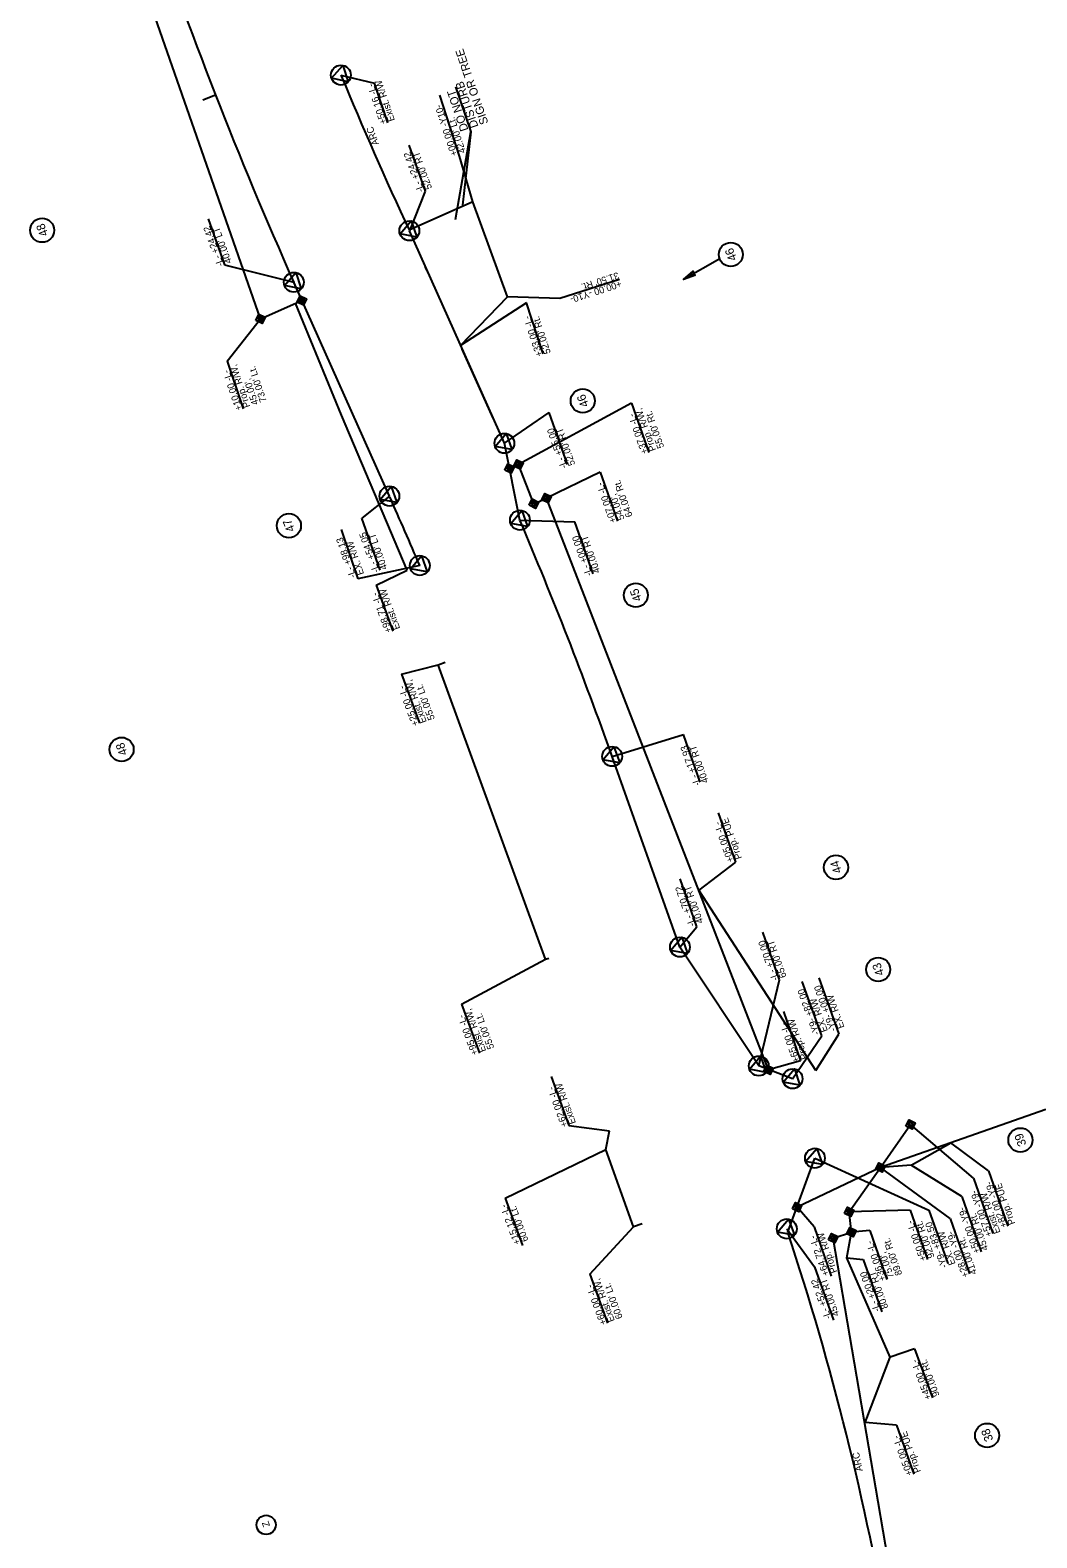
# Model space of a CAD drawing. Extents: x 1610947 to 1617684, y 899814 to 904658.
# Drawn here: x 1616090 to 1616822, y 902704 to 903801 of the extents above; entities that cross this region are included whole.
import ezdxf

# ---------------------------------------------------------------- set-up
doc = ezdxf.new("R2010")
doc.units = 0
for name, color, linetype in [('Default', 7, 'Continuous'), ('Prop Conc 1ft 6in Curb and Gutter', 7, 'Continuous'), ('Prop Dimension', 7, 'Continuous'), ('Prop EOT Dash', 7, 'Continuous'), ('Prop Hatching', 7, 'Continuous'), ('Prop Horizontal Alignment Curve and Spiral Data', 7, 'Continuous'), ('Prop Horizontal Alignment Direction Label', 7, 'Continuous'), ('Prop Horizontal Alignment Tick Label', 7, 'Continuous'), ('Prop Horizontal Alignment Tick Large', 7, 'Continuous'), ('Prop ROW Marker CELL', 7, 'Continuous'), ('Prop ROW RW Lines', 7, 'Continuous'), ('Prop ROW Station Offsets', 7, 'Continuous'), ('Prop Terminator CELL', 7, 'Continuous'), ('Scratch_Level_3', 7, 'Continuous'), ('Typical Terminator CELL', 7, 'Continuous')]:
    doc.layers.add(name, color=color, linetype=linetype)

msp = doc.modelspace()

# ---------------------------------------------------------------- linework, layer by layer
at = {"layer": 'Default'}
msp.add_circle((1616261.7, 902713.8), 7, dxfattribs=at)
at = {"layer": 'Prop Conc 1ft 6in Curb and Gutter'}
for p, q in [((1616402.3, 903709.6), (1616388, 903753.9)), ((1616412.1, 903676.4), (1616402.3, 903709.6)), ((1616518.8, 903620), (1616475.4, 903606)), ((1616475.4, 903606), (1616437.2, 903607.3)), ((1616451.2, 903602.9), (1616403.2, 903571.9)), ((1616463.2, 903565.7), (1616451.2, 903602.9)), ((1616341.8, 903397.5), (1616353.9, 903364.1)), ((1616360.3, 903332.8), (1616386.9, 903339.5)), ((1616360.3, 903332.8), (1616373.3, 903297.1)), ((1616590.5, 903231.8), (1616603, 903196)), ((1616603, 903196), (1616576.5, 903175.5)), ((1616403.9, 903092.6), (1616465, 903125.3)), ((1616663.7, 903111.7), (1616678.2, 903070.9)), ((1616403.9, 903092.6), (1616416.9, 903056.9)), ((1616661.6, 903044.5), (1616678.2, 903070.9)), ((1616469.1, 903040.1), (1616481.8, 903004.4)), ((1616787.2, 902971.5), (1616759.8, 902991.8)), ((1616435.7, 902951.6), (1616508.9, 902987)), ((1616767.7, 902952.8), (1616730.9, 902975.4)), ((1616787.2, 902971.5), (1616801.3, 902931.2)), ((1616435.7, 902951.6), (1616448.3, 902917.1)), ((1616767.7, 902952.8), (1616781.8, 902912.5)), ((1616497.1, 902896.1), (1616529, 902930.6)), ((1616684, 902908.1), (1616696, 902906.8)), ((1616696, 902906.8), (1616709.5, 902868.9)), ((1616497.1, 902896.1), (1616510.1, 902860.5)), ((1616733.3, 902841.8), (1616746.3, 902806.2)), ((1616720.1, 902786.4), (1616732.7, 902750.7))]:
    msp.add_line(p, q, dxfattribs=at)
for points in [[(1616341.8, 903397.5), (1616364.4, 903408.5)], [(1616481.8, 903004.4), (1616511.4, 903000.6)], [(1616733.3, 902841.8), (1616715.6, 902835.9)], [(1616720.1, 902786.4), (1616697.4, 902788.2)]]:
    msp.add_lwpolyline(points, dxfattribs=at)
at = {"layer": 'Prop Dimension'}
for p, q in [((1616399.4, 903760), (1616410.5, 903727.3)), ((1616399.4, 903663.6), (1616410.5, 903727.3)), ((1616410.5, 903727.3), (1616404.5, 903674))]:
    msp.add_line(p, q, dxfattribs=at)
at = {"layer": 'Prop EOT Dash'}
for points in [[(1616284.4, 903603.5), (1616286.5, 903608.1), (1616291.2, 903605.9), (1616289, 903601.3)], [(1616286.1, 903604.1), (1616287.2, 903606.4), (1616289.5, 903605.3), (1616288.4, 903603)], [(1616254.3, 903590), (1616256.4, 903594.6), (1616261, 903592.5), (1616258.9, 903587.9)], [(1616256, 903590.6), (1616257, 903592.9), (1616259.3, 903591.9), (1616258.3, 903589.6)], [(1616435.3, 903481.2), (1616437.5, 903485.8), (1616442.1, 903483.6), (1616439.9, 903479)], [(1616437, 903481.8), (1616438.1, 903484.1), (1616440.4, 903483), (1616439.3, 903480.7)], [(1616441.8, 903484), (1616444, 903488.6), (1616448.6, 903486.4), (1616446.4, 903481.8)], [(1616443.5, 903484.6), (1616444.6, 903486.9), (1616446.9, 903485.8), (1616445.8, 903483.5)], [(1616462.2, 903459.5), (1616464.4, 903464.1), (1616469, 903461.9), (1616466.8, 903457.3)], [(1616463.9, 903460.1), (1616465, 903462.4), (1616467.3, 903461.3), (1616466.2, 903459)], [(1616453, 903455.6), (1616455.2, 903460.2), (1616459.8, 903458), (1616457.6, 903453.4)], [(1616454.7, 903456.2), (1616455.8, 903458.5), (1616458.1, 903457.4), (1616457, 903455.1)], [(1616623.8, 903043.7), (1616626, 903048.3), (1616630.6, 903046.2), (1616628.4, 903041.6)], [(1616625.5, 903044.3), (1616626.6, 903046.6), (1616628.9, 903045.6), (1616627.8, 903043.3)], [(1616727.1, 903004), (1616729.3, 903008.6), (1616733.9, 903006.4), (1616731.7, 903001.8)], [(1616728.8, 903004.6), (1616729.9, 903006.9), (1616732.2, 903005.8), (1616731.1, 903003.5)], [(1616705.2, 902972.6), (1616707.4, 902977.2), (1616712, 902975), (1616709.8, 902970.4)], [(1616706.9, 902973.2), (1616708, 902975.5), (1616710.3, 902974.4), (1616709.2, 902972.1)], [(1616644.5, 902943.8), (1616646.7, 902948.4), (1616651.2, 902946.2), (1616649.1, 902941.6)], [(1616646.2, 902944.4), (1616647.3, 902946.7), (1616649.6, 902945.6), (1616648.5, 902943.3)], [(1616682.4, 902940.4), (1616684.6, 902945), (1616689.2, 902942.8), (1616687, 902938.2)], [(1616684.1, 902941), (1616685.2, 902943.3), (1616687.5, 902942.2), (1616686.4, 902939.9)], [(1616670.8, 902921.2), (1616673, 902925.8), (1616677.6, 902923.6), (1616675.4, 902919)], [(1616672.5, 902921.8), (1616673.6, 902924.1), (1616675.9, 902923), (1616674.8, 902920.7)], [(1616684.1, 902925.5), (1616686.3, 902930.1), (1616690.9, 902927.9), (1616688.7, 902923.3)], [(1616685.8, 902926.1), (1616686.9, 902928.4), (1616689.2, 902927.3), (1616688.1, 902925)]]:
    msp.add_lwpolyline(points, close=True, dxfattribs=at)
at = {"layer": 'Prop Hatching'}
msp.add_line((1616591.6, 903634.9), (1616565.3, 903620), dxfattribs=at)
for centre in [(1616098.8, 903655.7), (1616599.7, 903638.1), (1616492, 903531.6), (1616278.3, 903440.8), (1616530.6, 903390.2), (1616156.6, 903278), (1616676.2, 903192.2), (1616706.9, 903117.9), (1616810.3, 902993.8), (1616786.1, 902778.9)]:
    msp.add_circle(centre, 8.75, dxfattribs=at)
at = {"layer": 'Prop Horizontal Alignment Curve and Spiral Data'}
for p, q in [((1616776.2, 902966), (1616730.5, 903005.2)), ((1616776.2, 902966), (1616790.3, 902925.8)), ((1616660.3, 902930.6), (1616647.9, 902945)), ((1616660.3, 902930.6), (1616672.8, 902894.8))]:
    msp.add_line(p, q, dxfattribs=at)
at = {"layer": 'Prop Horizontal Alignment Direction Label'}
for p, q in [((1616257.7, 903591.2), (1616125.4, 903970.5)), ((1616257.7, 903591.2), (1616287.8, 903604.7)), ((1616438.7, 903482.4), (1616445.2, 903485.2)), ((1616456.4, 903456.8), (1616445.2, 903485.2)), ((1616456.4, 903456.8), (1616465.6, 903460.7)), ((1616627.2, 903045), (1616465.6, 903460.7)), ((1616685.8, 902941.6), (1616708.6, 902973.8)), ((1616687.5, 902926.7), (1616685.8, 902941.6)), ((1616674.2, 902922.4), (1616687.5, 902926.7)), ((1616749.1, 902482.9), (1616674.2, 902922.4))]:
    msp.add_line(p, q, dxfattribs=at)
at = {"layer": 'Prop Horizontal Alignment Tick Label'}
for p, q in [((1616233.3, 903560.5), (1616245, 903525.7)), ((1616527.5, 903529.9), (1616540, 903494.1)), ((1616504.7, 903479.8), (1616517.2, 903444)), ((1616638, 903087.3), (1616650.5, 903051.5)), ((1616759.3, 902936.8), (1616708.6, 902973.8)), ((1616730.1, 902942.8), (1616742.7, 902907)), ((1616759.3, 902936.8), (1616773.4, 902896.5)), ((1616700.7, 902928.1), (1616713.2, 902892.3))]:
    msp.add_line(p, q, dxfattribs=at)
for points in [[(1616233.3, 903560.5), (1616257.7, 903591.2)], [(1616527.5, 903529.9), (1616445.2, 903485.2)], [(1616504.7, 903479.8), (1616465.6, 903460.7)], [(1616650.5, 903051.5), (1616627.2, 903045)], [(1616730.1, 902942.8), (1616685.8, 902941.6)], [(1616700.7, 902928.1), (1616687.5, 902926.7)]]:
    msp.add_lwpolyline(points, dxfattribs=at)
at = {"layer": 'Prop Horizontal Alignment Tick Large'}
for q in [(1616730.5, 903005.2), (1616647.9, 902945)]:
    msp.add_line((1616708.6, 902973.8), q, dxfattribs=at)
at = {"layer": 'Prop ROW Marker CELL'}
for p, q in [((1616316.1, 903768.6), (1616316.1, 903768.6)), ((1616365.9, 903655.4), (1616365.9, 903655.4)), ((1616281.9, 903617.9), (1616281.9, 903617.9)), ((1616287.8, 903604.7), (1616287.8, 903604.7)), ((1616257.7, 903591.2), (1616257.7, 903591.2)), ((1616435, 903500.7), (1616435, 903500.7)), ((1616445.2, 903485.2), (1616445.2, 903485.2)), ((1616438.7, 903482.4), (1616438.7, 903482.4)), ((1616351.4, 903462.3), (1616351.4, 903462.3)), ((1616456.4, 903456.8), (1616456.4, 903456.8)), ((1616465.6, 903460.7), (1616465.6, 903460.7)), ((1616446.3, 903444.8), (1616446.3, 903444.8)), ((1616373.5, 903411.8), (1616373.5, 903411.8)), ((1616513.4, 903272.9), (1616513.4, 903272.9)), ((1616562.7, 903134.2), (1616562.7, 903134.2)), ((1616620, 903047.7), (1616620, 903047.7)), ((1616627.2, 903045), (1616627.2, 903045)), ((1616644.6, 903038.4), (1616644.6, 903038.4)), ((1616730.5, 903005.2), (1616730.5, 903005.2)), ((1616660.9, 902980.6), (1616660.9, 902980.6)), ((1616708.6, 902973.8), (1616708.6, 902973.8)), ((1616647.9, 902945), (1616647.9, 902945)), ((1616685.8, 902941.6), (1616685.8, 902941.6)), ((1616640.4, 902929.2), (1616640.4, 902929.2)), ((1616687.5, 902926.7), (1616687.5, 902926.7)), ((1616674.2, 902922.4), (1616674.2, 902922.4))]:
    msp.add_line(p, q, dxfattribs=at)
for points in [[(1616321.5, 903763.8), (1616309.3, 903766.3), (1616317.6, 903775.6)], [(1616371.3, 903650.6), (1616359.1, 903653.1), (1616367.3, 903662.5)], [(1616287.3, 903613.1), (1616275.1, 903615.6), (1616283.3, 903624.9)], [(1616440.5, 903496.1), (1616428.2, 903498.3), (1616436.3, 903507.8)], [(1616356.9, 903457.6), (1616344.6, 903459.9), (1616352.7, 903469.4)], [(1616451.8, 903440.1), (1616439.6, 903442.4), (1616447.6, 903451.9)], [(1616378.9, 903407.1), (1616366.7, 903409.3), (1616374.8, 903418.8)], [(1616518.9, 903268.2), (1616506.6, 903270.5), (1616514.7, 903280)], [(1616568.2, 903129.5), (1616555.9, 903131.8), (1616564, 903141.3)], [(1616625.5, 903043), (1616613.2, 903045.3), (1616621.3, 903054.8)], [(1616650, 903033.8), (1616637.8, 903036), (1616645.9, 903045.5)], [(1616666.4, 902975.9), (1616654.1, 902978.2), (1616662.2, 902987.7)], [(1616645.9, 902924.5), (1616633.6, 902926.7), (1616641.7, 902936.2)]]:
    msp.add_lwpolyline(points, close=True, dxfattribs=at)
for centre in [(1616316.1, 903768.6), (1616365.9, 903655.4), (1616281.9, 903617.9), (1616435, 903500.7), (1616351.4, 903462.3), (1616446.3, 903444.8), (1616373.5, 903411.8), (1616513.4, 903272.9), (1616562.7, 903134.2), (1616620, 903047.7), (1616644.6, 903038.4), (1616660.9, 902980.6), (1616640.4, 902929.2)]:
    msp.add_circle(centre, 7.2, dxfattribs=at)
at = {"layer": 'Prop ROW RW Lines'}
for p, q in [((1616435, 903500.7), (1616365.9, 903655.4)), ((1616378.9, 903626.3), (1616377.7, 903628.9)), ((1616351.4, 903462.3), (1616281.9, 903617.9)), ((1616426.9, 903519), (1616404.4, 903569.2)), ((1616446.3, 903444.8), (1616435, 903500.7)), ((1616562.7, 903134.2), (1616513.4, 903272.9)), ((1616620, 903047.7), (1616562.7, 903134.2)), ((1616644.6, 903038.4), (1616620, 903047.7)), ((1616641.2, 902926.8), (1616660.9, 902980.6))]:
    msp.add_line(p, q, dxfattribs=at)
for centre, radius, start, end in [((1619057.3, 904858.2), 3040, 198.4827, 204.0803), ((1619039, 904898.5), 2948, 202.5367, 204.9392), ((1613649, 902254.6), 2960, 23.0123, 24.0665), ((1613649, 902254.6), 3040, 19.5707, 23.048), ((1614715.5, 902288.7), 2028.6, 9.6706, 18.3345)]:
    msp.add_arc(centre, radius, start, end, dxfattribs=at)
at = {"layer": 'Prop ROW Station Offsets'}
for p, q in [((1616316.1, 903768.6), (1616340.5, 903762.7)), ((1616350.2, 903733.8), (1616340.5, 903762.7)), ((1616365.4, 903717.6), (1616377.4, 903684.1)), ((1616377.4, 903684.1), (1616365.9, 903655.4)), ((1616219.5, 903664.1), (1616231.5, 903630.6)), ((1616435, 903500.7), (1616467.7, 903523.2)), ((1616481, 903485.3), (1616467.7, 903523.2)), ((1616351.4, 903462.3), (1616331.4, 903446.2)), ((1616344.6, 903408.3), (1616331.4, 903446.2)), ((1616446.3, 903444.8), (1616486.3, 903443.6)), ((1616499.6, 903405.7), (1616486.3, 903443.6)), ((1616316.3, 903437.9), (1616328.5, 903402.1)), ((1616373.5, 903411.8), (1616328.5, 903402.1)), ((1616513.4, 903272.9), (1616565.3, 903288.9)), ((1616577.5, 903254.1), (1616565.3, 903288.9)), ((1616575.1, 903148.9), (1616562.8, 903183.9)), ((1616562.7, 903134.2), (1616575.1, 903148.9)), ((1616635.2, 903110.4), (1616622.9, 903145)), ((1616620, 903047.7), (1616635.2, 903110.4)), ((1616665.8, 903069.5), (1616651.6, 903109.2)), ((1616644.6, 903038.4), (1616665.8, 903069.5)), ((1616660.9, 902980.6), (1616743.7, 902942.7)), ((1616743.7, 902942.7), (1616757.5, 902903.9)), ((1616640.4, 902929.2), (1616660.5, 902901.5)), ((1616660.5, 902901.5), (1616674.3, 902862.7))]:
    msp.add_line(p, q, dxfattribs=at)
msp.add_lwpolyline([(1616231.5, 903630.6), (1616281.9, 903617.9)], dxfattribs=at)
at = {"layer": 'Prop Terminator CELL'}
msp.add_lwpolyline([(1616573.9, 903623.1), (1616565.3, 903620), (1616572.4, 903625.9), (1616572.2, 903623.9)], close=True, dxfattribs=at)
msp.add_lwpolyline([(1616573.9, 903623.1), (1616565.3, 903620), (1616572.4, 903625.9), (1616572.2, 903623.9)], close=True, dxfattribs=at)
at = {"layer": 'Scratch_Level_3'}
for p, q in [((1616225, 903754), (1616215.7, 903750.3)), ((1616412.1, 903676.4), (1616365.7, 903655.9)), ((1616437.2, 903607.3), (1616412.1, 903676.4)), ((1616403.2, 903571.9), (1616437.2, 903607.3)), ((1616316.5, 903521.2), (1616283.2, 903602.7)), ((1616364.4, 903408.5), (1616316.5, 903521.2)), ((1616386.9, 903339.5), (1616391.9, 903341.4)), ((1616465, 903125.3), (1616386.9, 903339.5)), ((1616661.6, 903044.5), (1616576.5, 903175.5)), ((1616465, 903125.3), (1616467.4, 903126.1)), ((1616508.9, 902987), (1616511.4, 903000.6)), ((1616730.9, 902975.4), (1616759.8, 902991.8)), ((1616529, 902930.6), (1616508.9, 902987)), ((1616730.9, 902975.4), (1616708.6, 902973.8)), ((1616535.2, 902932.8), (1616529, 902930.6)), ((1616684, 902908.1), (1616687.5, 902926.7)), ((1616715.6, 902835.9), (1616684, 902908.1)), ((1616697.4, 902788.2), (1616715.6, 902835.9))]:
    msp.add_line(p, q, dxfattribs=at)
at = {"layer": 'Typical Terminator CELL'}
msp.add_line((1616828.9, 903016), (1616708.6, 902973.8), dxfattribs=at)

# ---------------------------------------------------------------- texts
at = {"layer": 'Default'}
msp.add_text('Z', height=5, rotation=109.5707, dxfattribs=at).set_placement((1616264.6, 902713.2))
at = {"layer": 'Prop Conc 1ft 6in Curb and Gutter'}
for s, rotation, p in [('+00.00 -Y10-', 107.893, (1616401, 903710.6)), ("42.00' Lt.", 107.893, (1616407, 903712.6)), ('+00.00 -Y10-', 197.893, (1616519.3, 903619.3)), ("31.50' Rt.", 197.893, (1616517.4, 903625.3)), ('+33.00 -L-', 107.893, (1616462.9, 903564.7)), ("52.00' Rt.", 107.893, (1616468.8, 903566.6)), ('+98.71 -L-', 110.0511, (1616353.2, 903363.9)), ('Exist. R/W', 110.0511, (1616359.3, 903366.1)), ('+25.00 -L-', 110.0511, (1616372.8, 903296)), ('Exist. R/W,', 110.0511, (1616378.6, 903298.1)), ("55.00' Lt.", 110.0511, (1616384.5, 903300.3)), ('+05.00 -L-', 109.3048, (1616602, 903196.9)), ('Prop. PUE', 109.3048, (1616607.9, 903199)), ('-Y9- +00.00', 109.5486, (1616676.5, 903073.8)), ('Exist. R/W,', 110.0511, (1616421.8, 903058.7)), ('EX. R/W', 109.5486, (1616682.4, 903075.9)), ('+95.00 -L-', 110.0511, (1616416, 903056.6)), ("55.00' Lt.", 110.0511, (1616427.7, 903060.9)), ('Exist. R/W', 109.5486, (1616487.1, 903006.3)), ('+62.00 -L-', 109.5486, (1616481.2, 903004.2)), ('+82.00 -Y9-', 109.3048, (1616800.8, 902931)), ('Prop. PUE', 109.3048, (1616806.7, 902933.1)), ('+15.12 -L-', 110.0511, (1616446.8, 902918.7)), ("60.00' Lt.", 110.0511, (1616452.6, 902920.8)), ('+50.00 -Y9-', 109.3048, (1616781.2, 902912.3)), ("45.00' Rt.", 109.3048, (1616787.1, 902914.3)), ('Exist. R/W,', 110.0511, (1616515.4, 902862.4)), ('-L- +20.00', 109.5486, (1616708.4, 902869.8)), ("80.00' RT", 109.5486, (1616714.3, 902871.9)), ('+60.00 -L-', 110.0511, (1616509.5, 902860.3)), ("60.00' Lt.", 110.0511, (1616521.2, 902864.6)), ('+45.00 -L-', 110.0511, (1616745.7, 902805.9)), ("90.00' Rt.", 110.0511, (1616751.6, 902808.1)), ('Prop. PUE', 109.4757, (1616738, 902752.6)), ('+05.00 -L-', 109.4757, (1616732.1, 902750.5))]:
    msp.add_text(s, height=5, rotation=rotation, dxfattribs=at).set_placement(p)
at = {"layer": 'Prop Dimension'}
for s, p in [('SIGN OR TREE', (1616423.4, 903733.8)), ('DISTURB', (1616416.2, 903731.3)), ('DO NOT ', (1616408.9, 903728.9))]:
    msp.add_text(s, height=6, rotation=108.7326, dxfattribs=at).set_placement(p)
at = {"layer": 'Prop Hatching'}
for s, rotation, p in [('48', 111.3527, (1616103.4, 903652.6)), ('46', 111.3527, (1616604.3, 903634.8)), ('46', 110.62, (1616496.6, 903528.3)), ('47', 112.5109, (1616282.9, 903437.7)), ('45', 110.0073, (1616535.1, 903386.9)), ('48', 109.7977, (1616161.1, 903274.8)), ('44', 108.3838, (1616680.6, 903188.9)), ('43', 110.0991, (1616711.4, 903114.6)), ('39', 110.4882, (1616814.8, 902990.6)), ('38', 110.8797, (1616790.7, 902775.8))]:
    msp.add_text(s, height=6.25, rotation=rotation, dxfattribs=at).set_placement(p)
at = {"layer": 'Prop Horizontal Alignment Curve and Spiral Data'}
for s, p in [('+57.00 -Y9-', (1616790, 902924.5)), ('Exist. R/W', (1616795.9, 902926.6)), ('Prop. R/W', (1616677.2, 902897.9)), ('+64.72 -L-', (1616671.3, 902895.9))]:
    msp.add_text(s, height=5, rotation=109.3048, dxfattribs=at).set_placement(p)
at = {"layer": 'Prop Horizontal Alignment Tick Label'}
for s, rotation, p in [('+10.00 -L-', 108.5432, (1616244.4, 903525.5)), ('Prop. R/W,', 108.5432, (1616250.3, 903527.5)), ("73.00' Lt.", 108.5432, (1616262.2, 903531.5)), ("45.00',", 108.5432, (1616256.3, 903529.5)), ('+37.00 -L-', 109.3048, (1616539.5, 903493.9)), ('Prop. R/W,', 109.3048, (1616545.4, 903495.9)), ("55.00' Rt.", 109.3048, (1616551.3, 903498)), ("64.00' Rt.", 109.3048, (1616528.4, 903447.9)), ('+07.00 -L-', 109.3048, (1616516.6, 903443.8)), ("54.00',", 109.3048, (1616522.5, 903445.8)), ('+65.00 -L-', 109.3048, (1616649.9, 903051.3)), ('Prop. R/W', 109.3048, (1616655.8, 903053.4)), ('+50.00 -L-', 109.3048, (1616742.1, 902906.8)), ("92.00' Rt.", 109.3048, (1616748, 902908.8)), ('+28.00 -Y9-', 109.3048, (1616772.9, 902894.8)), ('+36.00 -L-', 109.3048, (1616712.6, 902892.1)), ("89.00' Rt.", 109.3048, (1616724.4, 902896.2)), ("41.00' Rt.", 109.3048, (1616778.8, 902896.9)), ("75.00',", 109.3048, (1616718.5, 902894.2))]:
    msp.add_text(s, height=5, rotation=rotation, dxfattribs=at).set_placement(p)
at = {"layer": 'Prop ROW Station Offsets'}
for s, rotation, p in [('+50.16 -L-', 108.5432, (1616349.5, 903733.8)), ('Exist. R/W', 108.5432, (1616355.4, 903735.8)), ('ARC', 109.686, (1616343.9, 903718.4)), ('-L- +24.42', 109.686, (1616376.6, 903684.3)), ("52.00' RT", 109.686, (1616382.5, 903686.4)), ('-L- +24.42', 109.686, (1616230.9, 903630.4)), ("40.00' LT", 109.686, (1616236.8, 903632.5)), ('-L- +55.00', 109.3048, (1616480.7, 903483.3)), ("52.00' RT", 109.3048, (1616486.6, 903485.4)), ('-L- +98.13', 108.8793, (1616327.1, 903403.7)), ('EX. R/W', 108.8793, (1616333, 903405.8)), ('-L- +54.05', 109.3048, (1616344.1, 903407.6)), ("40.00' LT", 109.3048, (1616350, 903409.7)), ('-L- +00.00', 109.3048, (1616498.9, 903405.1)), ("40.00' RT", 109.3048, (1616504.8, 903407.1)), ('-L- +17.93', 109.3048, (1616577.7, 903252.4)), ("40.00' RT", 109.3048, (1616583.6, 903254.4)), ('-L- +70.72', 109.3048, (1616573.9, 903150.2)), ("40.00' RT", 109.3048, (1616579.8, 903152.3)), ('-L- +70.00', 109.4757, (1616634.4, 903110.7)), ("65.00' RT", 109.4757, (1616640.3, 903112.7)), ('-Y9- +82.00', 109.6883, (1616664.5, 903071.2)), ('EX. R/W', 109.6883, (1616670.3, 903073.3)), ('-Y9- +83.50', 109.5486, (1616757.3, 902901.7)), ('EX. R/W', 109.5486, (1616763.2, 902903.8)), ('-L- +52.42', 109.5486, (1616672.8, 902864.4)), ("45.00' RT", 109.5486, (1616678.7, 902866.5)), ('ARC', 101.6131, (1616695.7, 902753.2))]:
    msp.add_text(s, height=5, rotation=rotation, dxfattribs=at).set_placement(p)

doc.saveas('drawing.dxf')
